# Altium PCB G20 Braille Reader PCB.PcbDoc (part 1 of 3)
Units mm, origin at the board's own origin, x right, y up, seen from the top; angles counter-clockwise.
Board outline 160.1 x 170.2 mm, 2 copper layers (Top Layer, Bottom Layer); 206 components, 272 nets, 975 pads, 345 vias.
Unrouted connection lines stored in the file: 1.
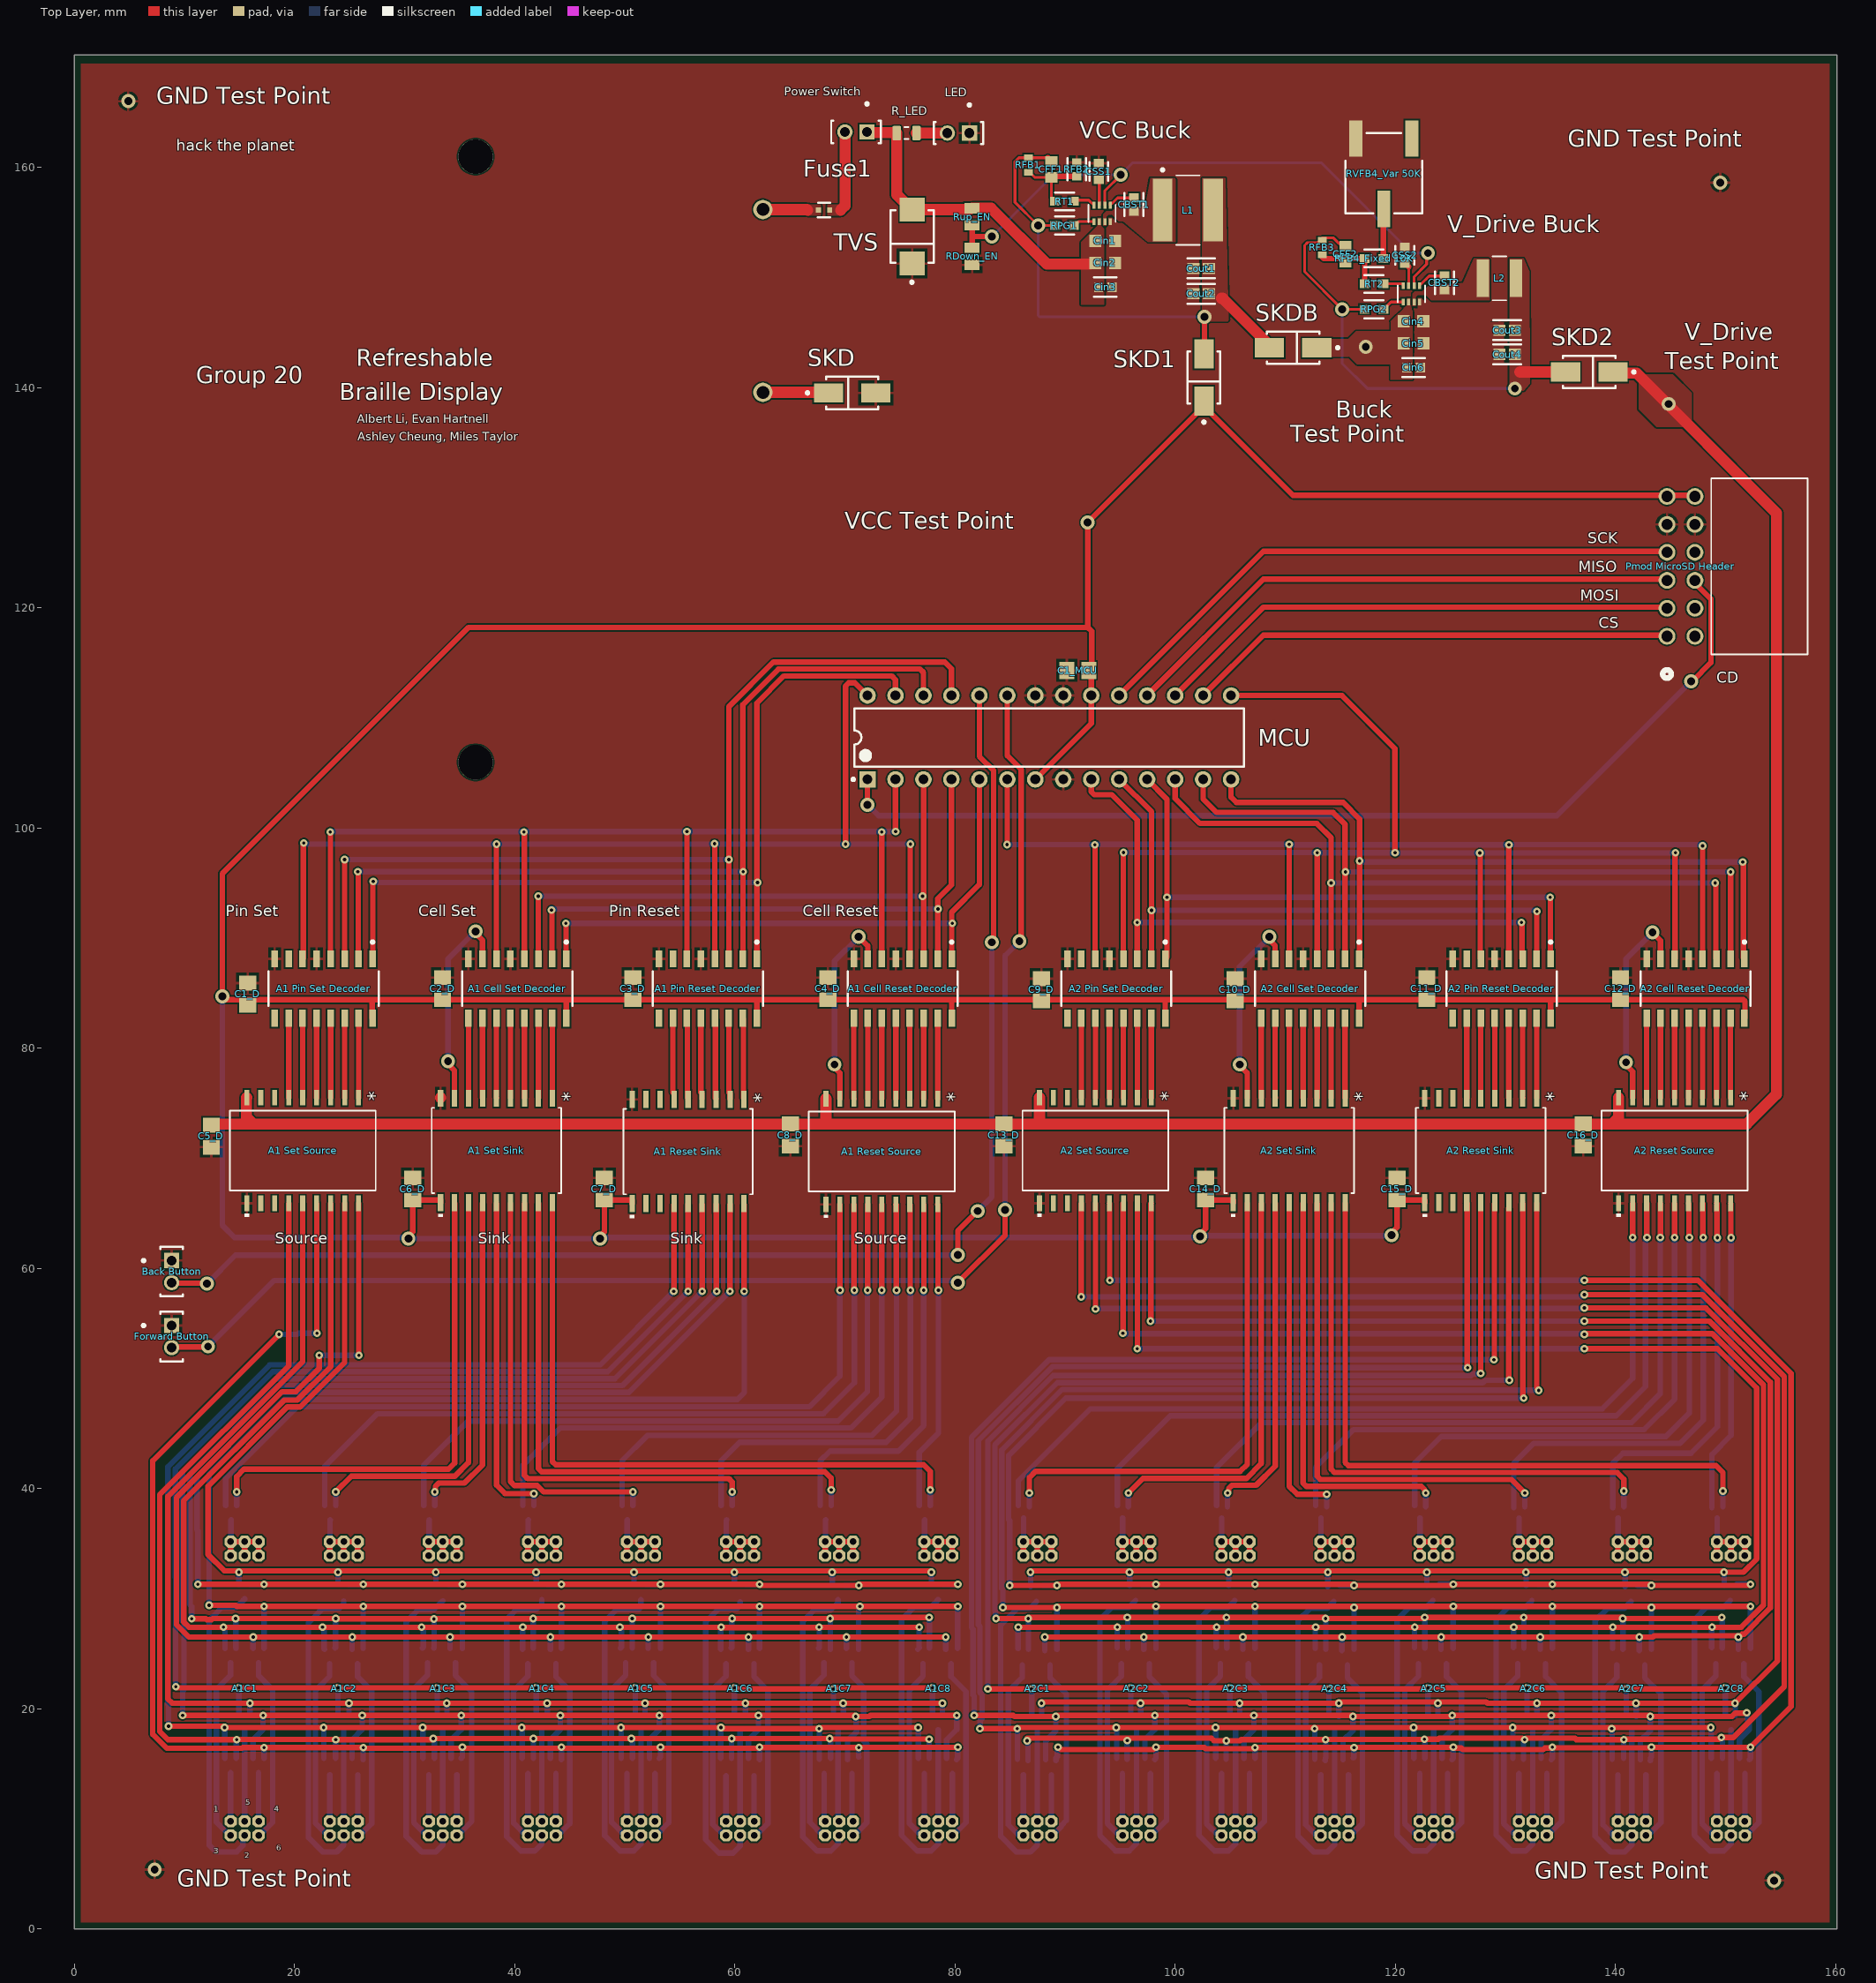
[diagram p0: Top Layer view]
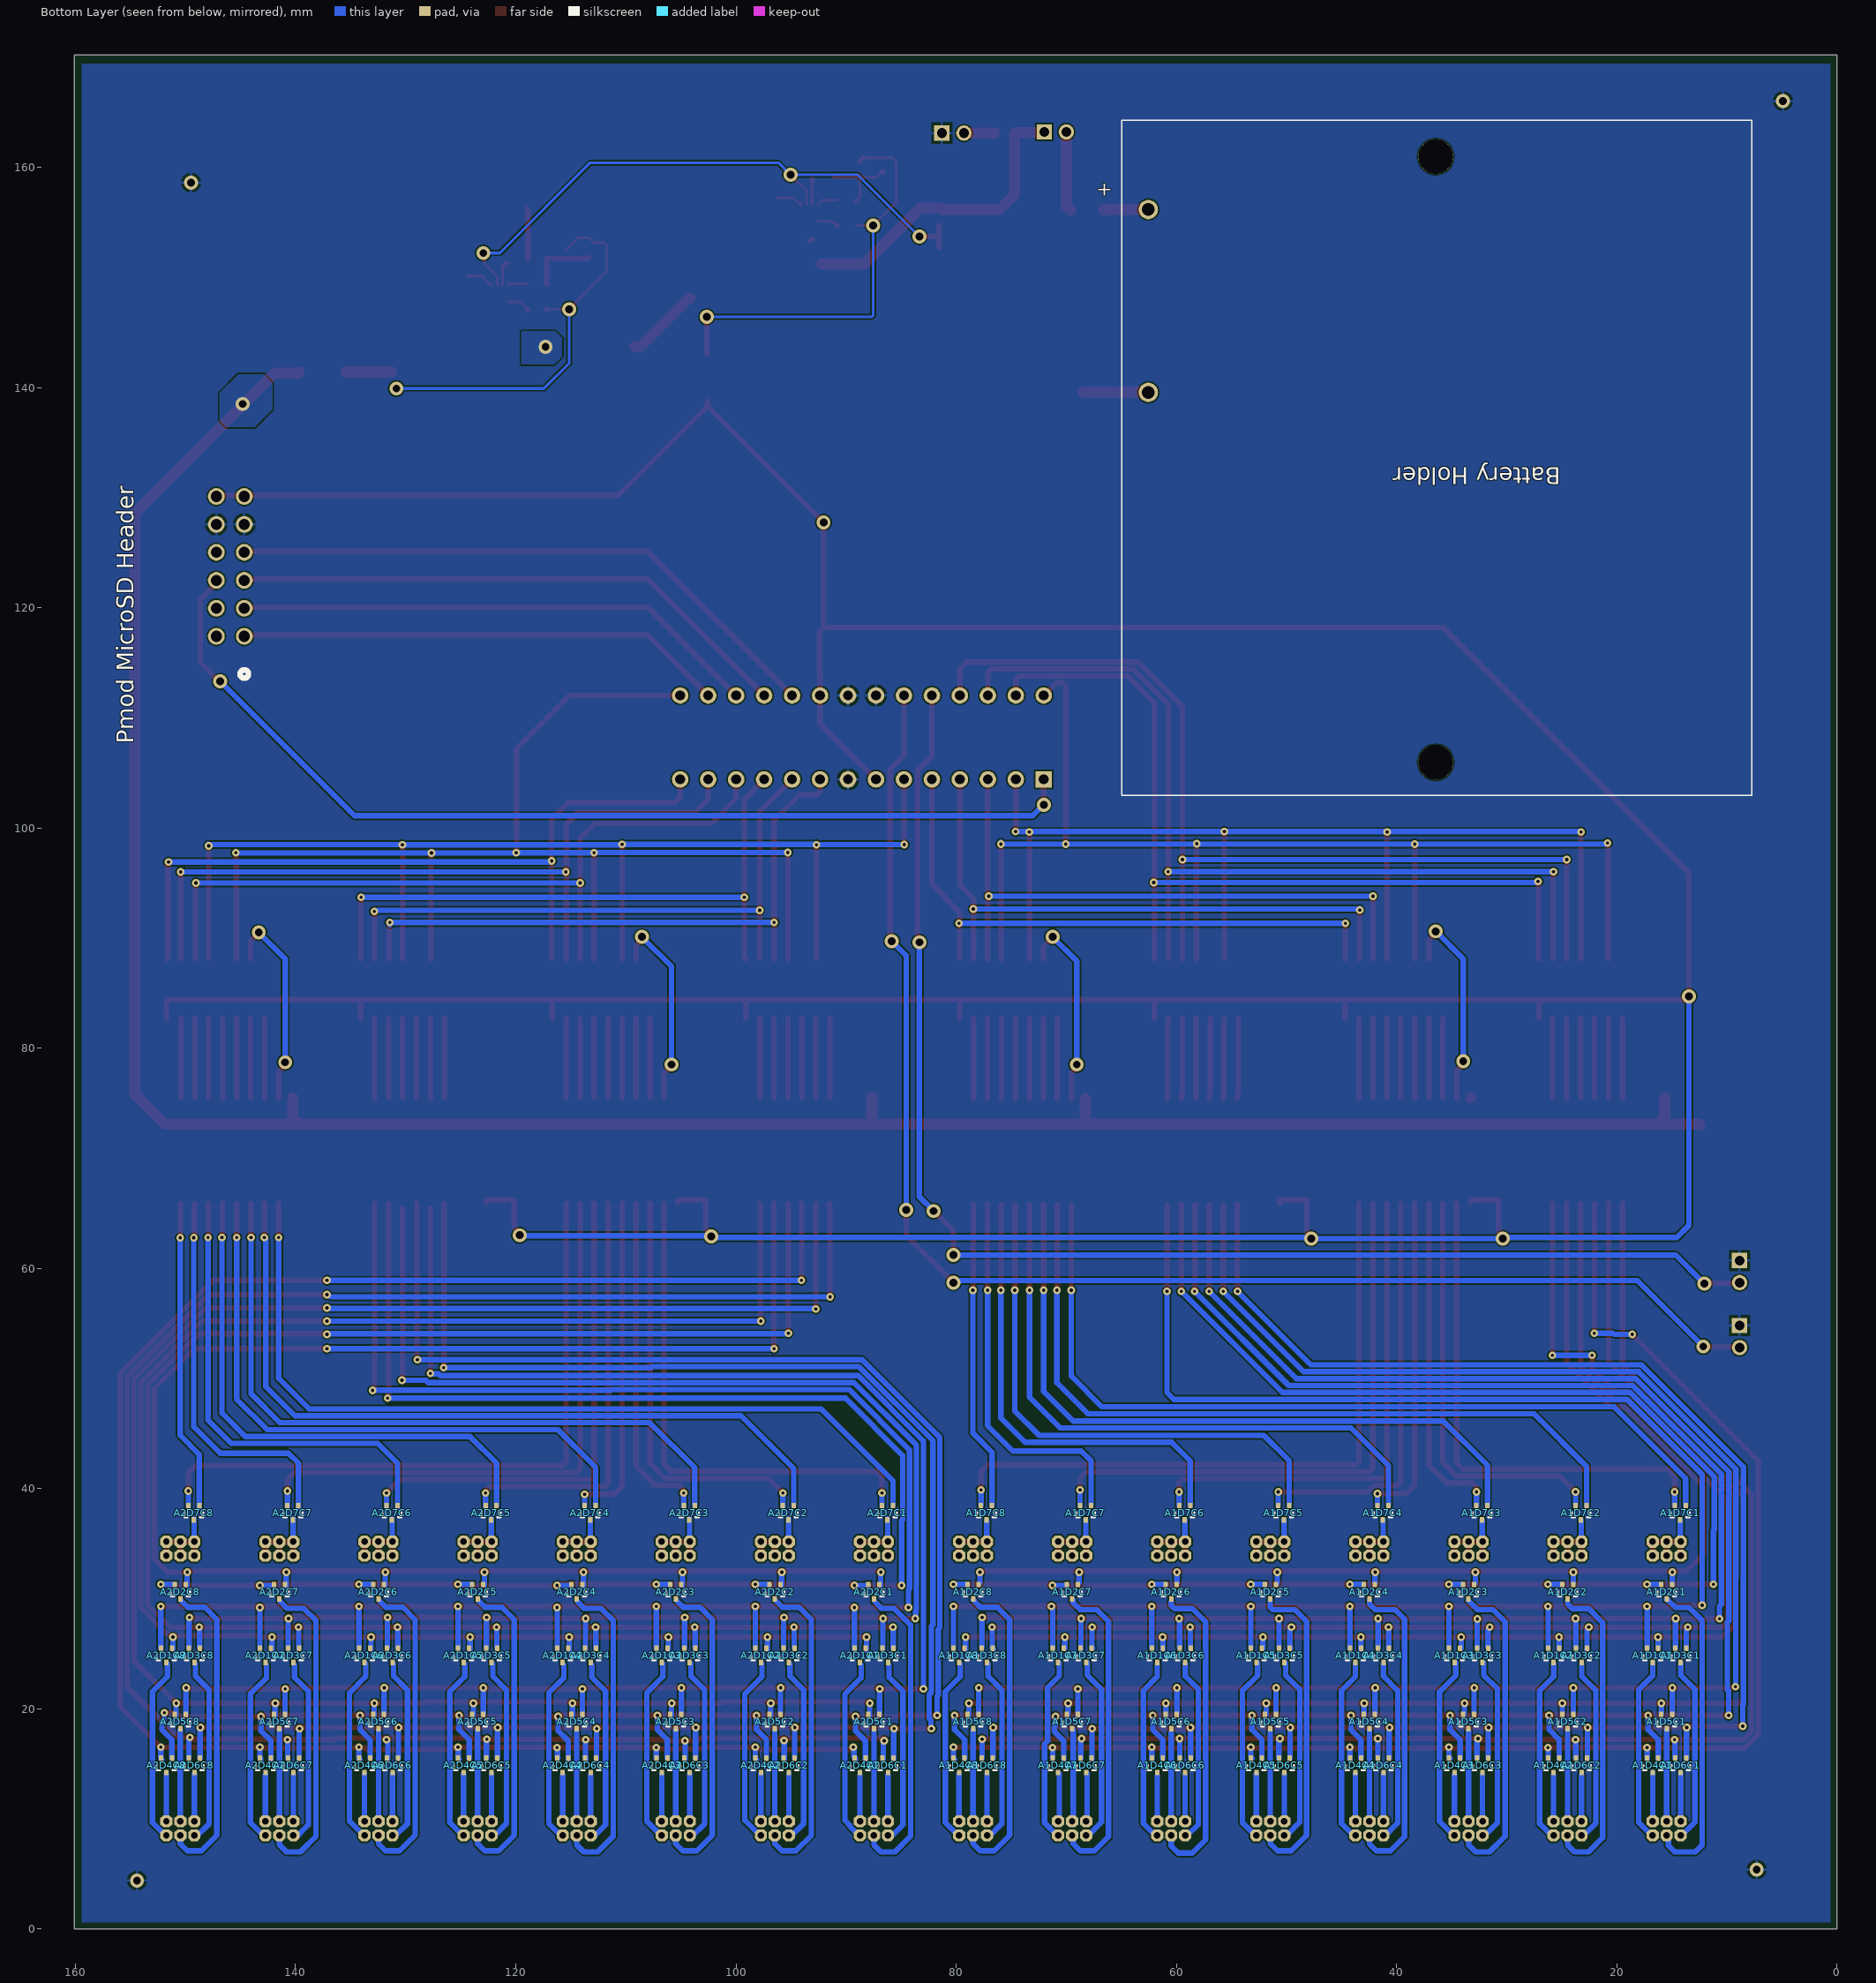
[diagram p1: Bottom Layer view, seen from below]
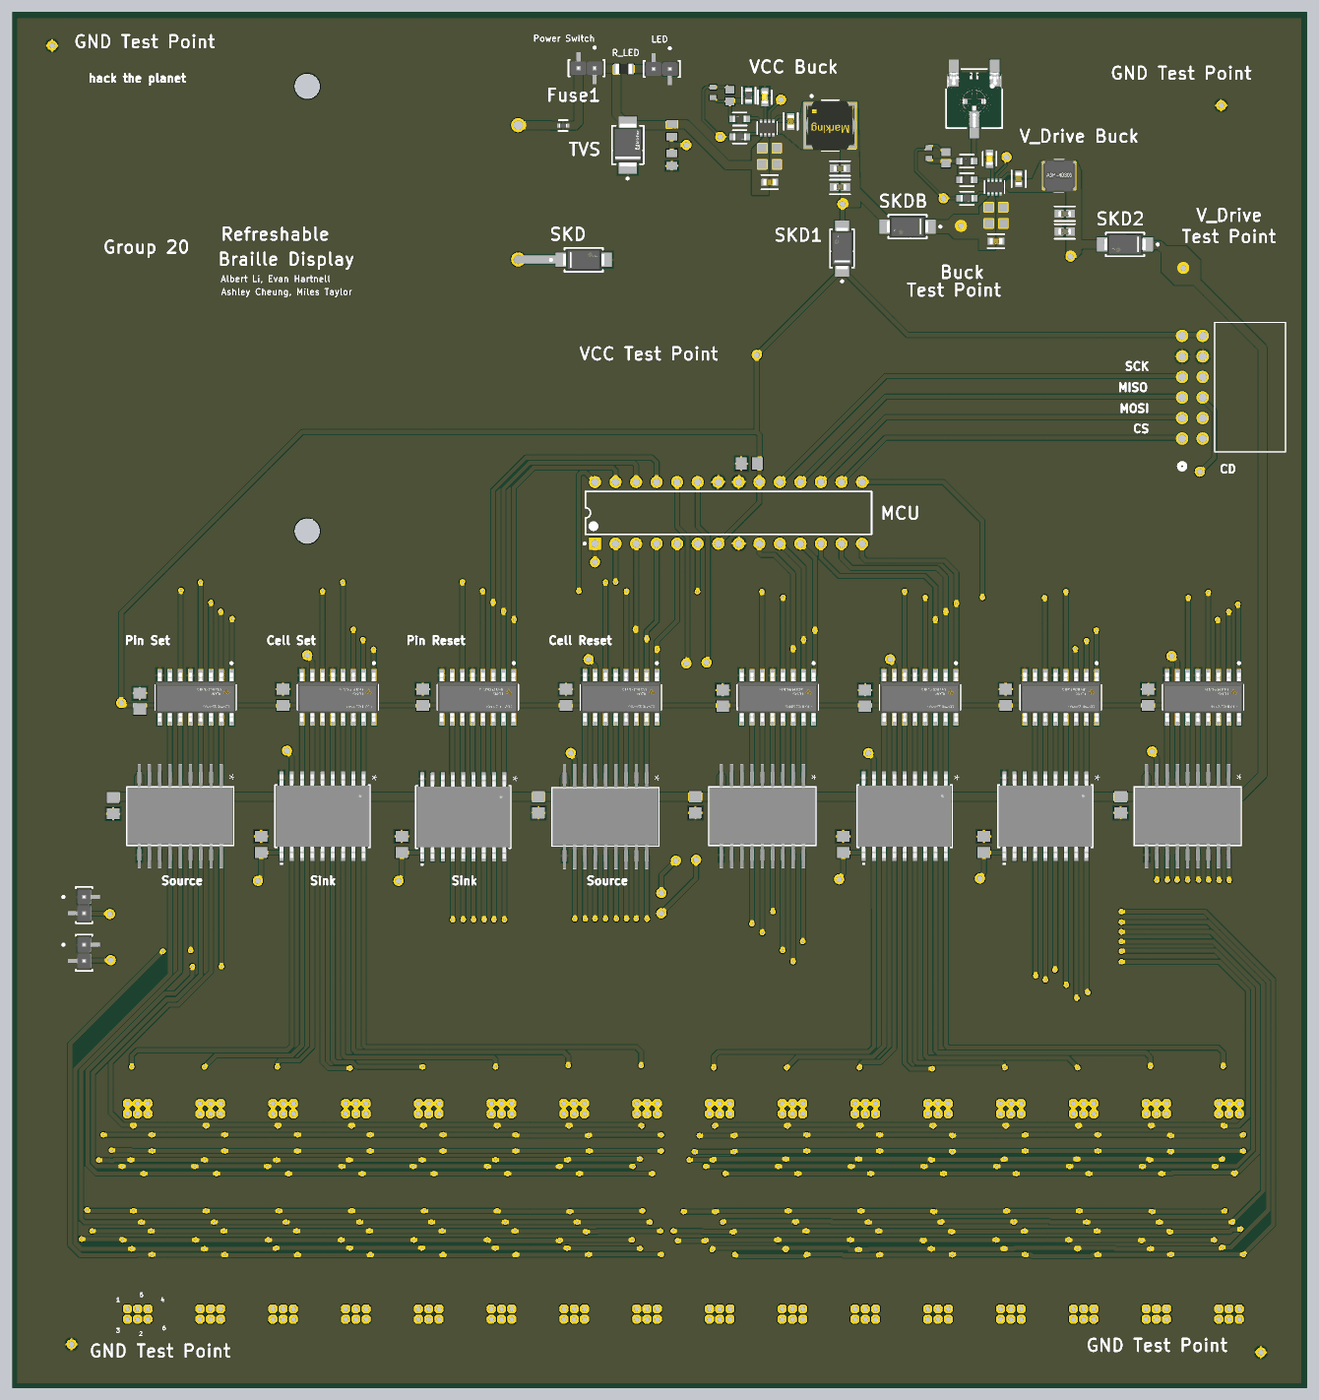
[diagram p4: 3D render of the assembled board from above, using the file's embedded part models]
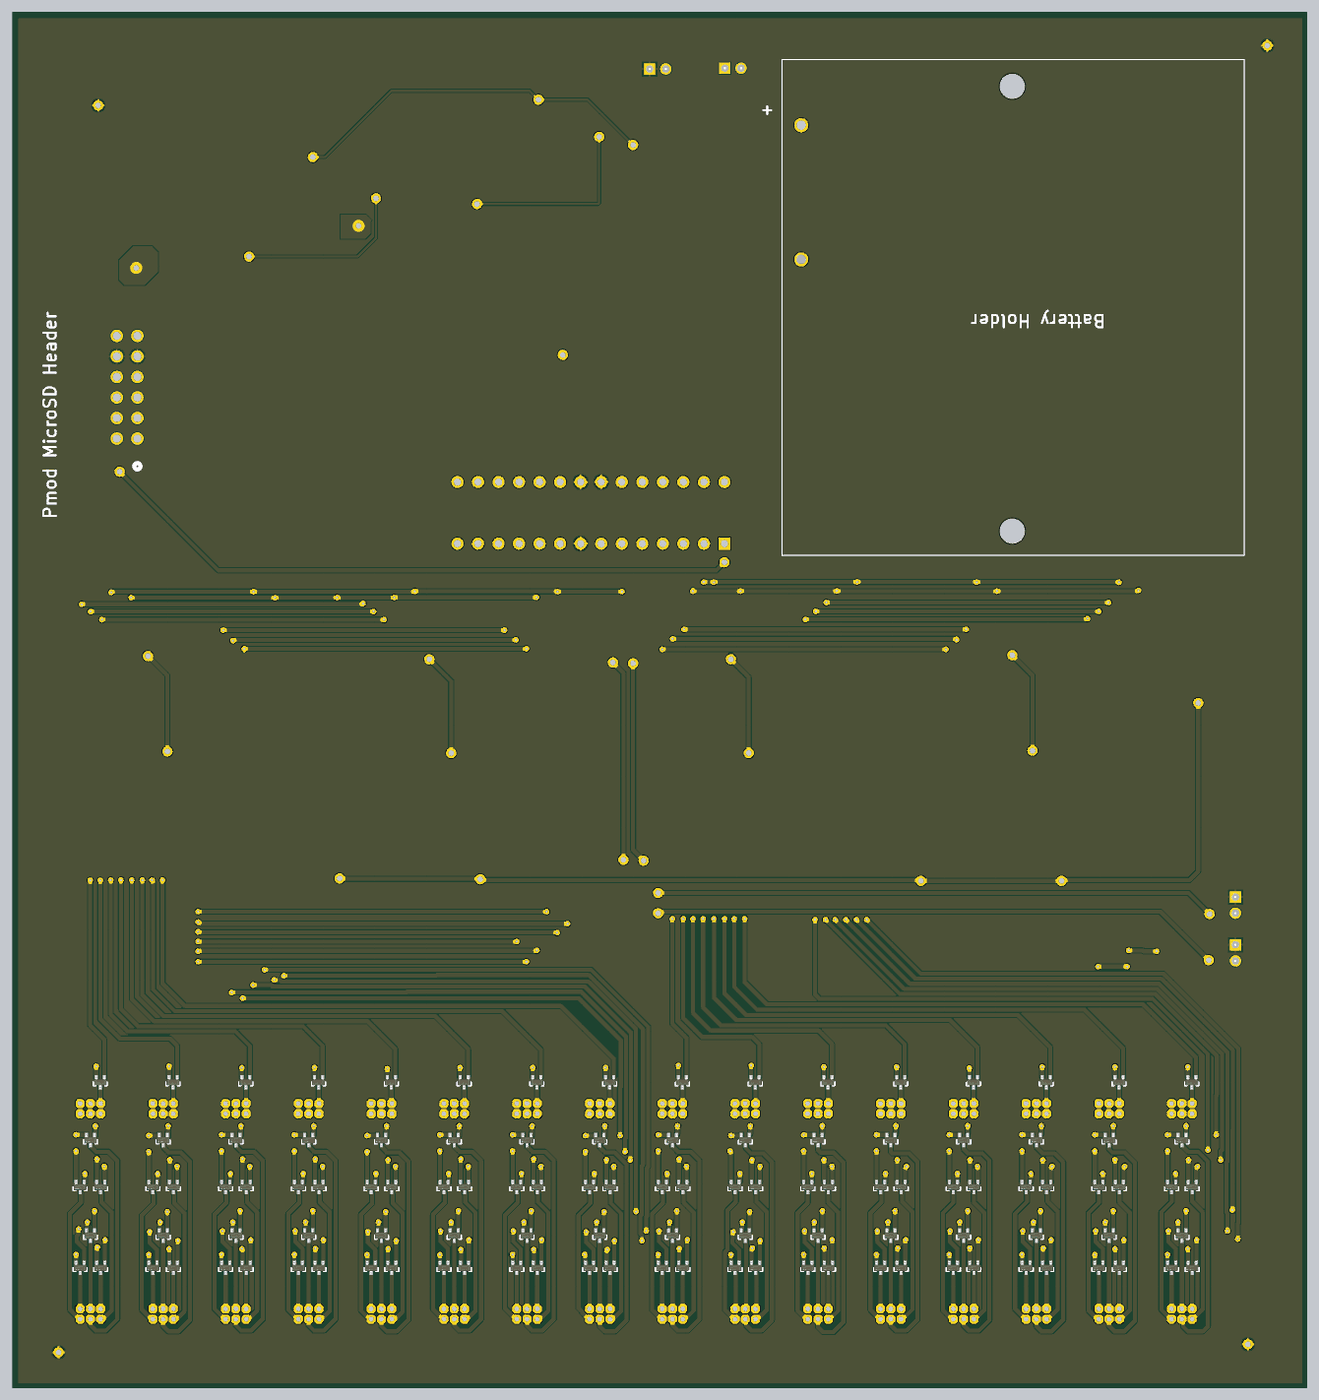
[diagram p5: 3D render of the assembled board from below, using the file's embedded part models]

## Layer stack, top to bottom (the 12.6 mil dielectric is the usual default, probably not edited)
Top Solder: solder mask 0.0102, Solder Resist, Dk 3.5
Top Layer: signal copper 0.0356
Dielectric 1: dielectric 0.32, FR-4, Dk 4.8
Bottom Layer: signal copper 0.0356
Bottom Solder: solder mask 0.0102, Solder Resist, Dk 3.5

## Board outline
0,0 0,170.2 160.1,170.2 160.1,0

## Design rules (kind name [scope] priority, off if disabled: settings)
BoardOutlineClearance [All] p1: gap=0.5 ignorepadtopadclearanceinfootprint=FALSE
Clearance [All] p1: gap=0.127 ignorepadtopadclearanceinfootprint=TRUE
HoleSize [All] p1: absolutevalues=TRUE maxlimit=40 minlimit=0.3 maxpercent=80.000 minpercent=20.000
MinimumAnnularRing [All] p1: minimumring=0.18
MinimumSolderMaskSliver [All] p1: minsoldermaskwidth=0.2
PolygonConnect [All] p1: connectstyle=Relief reliefconductorwidth=0.254 reliefentries=4 polygonreliefangle="90 Angle" airgapwidth=0.254
RoutingVias [All] p1: holewidth=0.3 width=0.6 viastyle="Through Hole" minholewidth=0.18 minwidth=0.6 maxholewidth=0.711 maxwidth=1.27
SolderMaskExpansion [All] p1: expansion=0.102 istentingtop=FALSE
SupplyNets "Schematic Supply Nets_13" [InNet('VCC1')] p1: voltage=0.000
SupplyNets "Schematic Supply Nets_4" [InNet('V_Drive1')] p2: voltage=0.000
SupplyNets "Schematic Supply Nets_1" [InNet('VCC_Filtered')] p3: voltage=0.000
SupplyNets "Schematic Supply Nets_12" [InNet('VSW2')] p4: voltage=0.000
SupplyNets "Schematic Supply Nets_11" [InNet('VPG1')] p5: voltage=0.000
SupplyNets "Schematic Supply Nets_10" [InNet('Vin')] p6: voltage=0.000
SupplyNets "Schematic Supply Nets_9" [InNet('VSW1')] p7: voltage=0.000
SupplyNets "Schematic Supply Nets_8" [InNet('VFB1')] p8: voltage=0.000
SupplyNets "Schematic Supply Nets_7" [InNet('VEN_Buck')] p9: voltage=0.000
SupplyNets "Schematic Supply Nets_6" [InNet('VFB2')] p10: voltage=0.000
SupplyNets "Schematic Supply Nets_5" [InNet('VPG2')] p11: voltage=0.000
SupplyNets "Schematic Supply Nets_3" [InNet('VCC')] p12: voltage=0.000
SupplyNets "Schematic Supply Nets_2" [InNet('GND')] p13: voltage=0.000
SupplyNets "Schematic Supply Nets" [InNet('V_Drive')] p14: voltage=0.000
Width [All] p1: maxlimit=1.016 minlimit=0.127 preferedwidth=1.016 bottomlayer_prefwidth=0.254 minimp=50.000000 maximp=50.000000 favimp=50.000000
28 further rules are at their usual default settings.

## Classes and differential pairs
component class "Power and Voltage Regulation Schematic": "Battery Holder" CBST1 CBST2 CFF1 CFF2 Cin1 Cin2 Cin3 Cin4 Cin5 Cin6 Cout1 Cout2 Cout3 Cout4 CSS1 CSS2 Fuse1 L1 L2 LED "Power Switch" R_LED RDown_EN RFB1 RFB2 RFB3 "RFB4_Fixed 10K" RPG1 RPG2 RT1 RT2 Rup_EN "RVFB4_Var 50K" SKD SKD1 SKD2 SKDB TVS "V_Drive Buck" "VCC Buck"
component class "MCU Schematic": "Back Button" C1_MCU "Forward Button" MCU "Pmod MicroSD Header"
component class "Array 2 Cell Driving Schematic": "A2 Cell Reset Decoder" "A2 Cell Set Decoder" "A2 Pin Reset Decoder" "A2 Pin Set Decoder" "A2 Reset Sink" "A2 Reset Source" "A2 Set Sink" "A2 Set Source" C9_D C10_D C11_D C12_D C13_D C14_D C15_D C16_D
component class "Array 2 Braille Cell Schematic": "119.724 mm" A2C1 A2C2 A2C3 A2C4 A2C5 A2C6 A2C7 A2C8 A2D1C1 A2D1C2 A2D1C3 A2D1C4 A2D1C5 A2D1C6 A2D1C7 A2D1C8 A2D2C1 A2D2C2 A2D2C3 A2D2C4 A2D2C5 A2D2C6 A2D2C7 A2D2C8 A2D3C1 A2D3C2 A2D3C3 A2D3C4 A2D3C5 A2D3C6 A2D3C7 A2D3C8 A2D4C1 A2D4C2 A2D4C3 A2D4C4 A2D4C5 A2D4C6 A2D4C7 A2D4C8 A2D5C1 A2D5C2 A2D5C3 A2D5C4 A2D5C5 A2D5C6 A2D5C7 A2D5C8 A2D6C1 A2D6C2 A2D6C3 A2D6C4 A2D6C5 A2D6C6 A2D6C7 A2D6C8 A2D7C1 A2D7C2 A2D7C3 A2D7C4 A2D7C5 A2D7C6 A2D7C7 A2D7C8
component class "Array 1 Cell Driving Schematic": "A1 Cell Reset Decoder" "A1 Cell Set Decoder" "A1 Pin Reset Decoder" "A1 Pin Set Decoder" "A1 Reset Sink" "A1 Reset Source" "A1 Set Sink" "A1 Set Source" C1_D C2_D C3_D C4_D C5_D C6_D C7_D C8_D
component class "Array 1 Braille Cell Schematic": A1C1 A1C2 A1C3 A1C4 A1C5 A1C6 A1C7 A1C8 A1D1C1 A1D1C2 A1D1C3 A1D1C4 A1D1C5 A1D1C6 A1D1C7 A1D1C8 A1D2C1 A1D2C2 A1D2C3 A1D2C4 A1D2C5 A1D2C6 A1D2C7 A1D2C8 A1D3C1 A1D3C2 A1D3C3 A1D3C4 A1D3C5 A1D3C6 A1D3C7 A1D3C8 A1D4C1 A1D4C2 A1D4C3 A1D4C4 A1D4C5 A1D4C6 A1D4C7 A1D4C8 A1D5C1 A1D5C2 A1D5C3 A1D5C4 A1D5C5 A1D5C6 A1D5C7 A1D5C8 A1D6C1 A1D6C2 A1D6C3 A1D6C4 A1D6C5 A1D6C6 A1D6C7 A1D6C8 A1D7C1 A1D7C2 A1D7C3 A1D7C4 A1D7C5 A1D7C6 A1D7C7 A1D7C8

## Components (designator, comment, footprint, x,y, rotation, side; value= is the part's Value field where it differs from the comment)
"A1 Cell Reset Decoder" "CD74HC238M96" FP-D0016A-MFG 75.246,85.405 r270 top
"A1 Cell Set Decoder" "CD74HC238M96" FP-D0016A-MFG 40.246,85.405 r270 top
"A1 Pin Reset Decoder" "CD74HC238M96" FP-D0016A-MFG 57.546,85.405 r270 top
"A1 Pin Set Decoder" "CD74HC238M96" FP-D0016A-MFG 22.646,85.405 r270 top
"A1 Reset Sink" "TBD62083AFWG,EL" P-SOP18-0812-1p27-001_TOS 55.746,70.605 r270 top
"A1 Reset Source" "TBD62783AFG,EL" SOP18-P-375-1p27_TOS 73.346,70.605 r270 top
"A1 Set Sink" "TBD62083AFWG,EL" P-SOP18-0812-1p27-001_TOS 38.346,70.705 r270 top
"A1 Set Source" "TBD62783AFG,EL" SOP18-P-375-1p27_TOS 20.746,70.705 r270 top
A1C1 "Braille Cell" BRAILLE-6 15.47,21.842 r180 top
A1C2 "Braille Cell" BRAILLE-6 24.47,21.842 r180 top
A1C3 "Braille Cell" BRAILLE-6 33.47,21.842 r180 top
A1C4 "Braille Cell" BRAILLE-6 42.47,21.842 r180 top
A1C5 "Braille Cell" BRAILLE-6 51.47,21.842 r180 top
A1C6 "Braille Cell" BRAILLE-6 60.47,21.842 r180 top
A1C7 "Braille Cell" BRAILLE-6 69.47,21.842 r180 top
A1C8 "Braille Cell" BRAILLE-6 78.47,21.842 r180 top
A1D1C1 "BAV99T-7-F" FP-SOT523-MFG 16.735,24.842 r270 bottom value=1.5pF
A1D1C2 "BAV99T-7-F" FP-SOT523-MFG 25.735,24.842 r270 bottom value=1.5pF
A1D1C3 "BAV99T-7-F" FP-SOT523-MFG 34.735,24.842 r270 bottom value=1.5pF
A1D1C4 "BAV99T-7-F" FP-SOT523-MFG 43.735,24.842 r270 bottom value=1.5pF
A1D1C5 "BAV99T-7-F" FP-SOT523-MFG 52.735,24.842 r270 bottom value=1.5pF
A1D1C6 "BAV99T-7-F" FP-SOT523-MFG 61.735,24.842 r270 bottom value=1.5pF
A1D1C7 "BAV99T-7-F" FP-SOT523-MFG 70.735,24.842 r270 bottom value=1.5pF
A1D1C8 "BAV99T-7-F" FP-SOT523-MFG 79.735,24.842 r270 bottom value=1.5pF
A1D2C1 "BAV99T-7-F" FP-SOT523-MFG 15.465,30.639 r270 bottom value=1.5pF
A1D2C2 "BAV99T-7-F" FP-SOT523-MFG 24.465,30.639 r270 bottom value=1.5pF
A1D2C3 "BAV99T-7-F" FP-SOT523-MFG 33.465,30.639 r270 bottom value=1.5pF
A1D2C4 "BAV99T-7-F" FP-SOT523-MFG 42.465,30.639 r270 bottom value=1.5pF
A1D2C5 "BAV99T-7-F" FP-SOT523-MFG 51.465,30.639 r270 bottom value=1.5pF
A1D2C6 "BAV99T-7-F" FP-SOT523-MFG 60.465,30.639 r270 bottom value=1.5pF
A1D2C7 "BAV99T-7-F" FP-SOT523-MFG 69.465,30.639 r270 bottom value=1.5pF
A1D2C8 "BAV99T-7-F" FP-SOT523-MFG 78.465,30.639 r270 bottom value=1.5pF
A1D3C1 "BAV99T-7-F" FP-SOT523-MFG 14.195,24.842 r270 bottom value=1.5pF
A1D3C2 "BAV99T-7-F" FP-SOT523-MFG 23.195,24.842 r270 bottom value=1.5pF
A1D3C3 "BAV99T-7-F" FP-SOT523-MFG 32.195,24.842 r270 bottom value=1.5pF
A1D3C4 "BAV99T-7-F" FP-SOT523-MFG 41.195,24.842 r270 bottom value=1.5pF
A1D3C5 "BAV99T-7-F" FP-SOT523-MFG 50.195,24.842 r270 bottom value=1.5pF
A1D3C6 "BAV99T-7-F" FP-SOT523-MFG 59.195,24.842 r270 bottom value=1.5pF
A1D3C7 "BAV99T-7-F" FP-SOT523-MFG 68.195,24.842 r270 bottom value=1.5pF
A1D3C8 "BAV99T-7-F" FP-SOT523-MFG 77.195,24.842 r270 bottom value=1.5pF
A1D4C1 "BAV99T-7-F" FP-SOT523-MFG 16.735,14.86 r270 bottom value=1.5pF
A1D4C2 "BAV99T-7-F" FP-SOT523-MFG 25.735,14.86 r270 bottom value=1.5pF
A1D4C3 "BAV99T-7-F" FP-SOT523-MFG 34.735,14.86 r270 bottom value=1.5pF
A1D4C4 "BAV99T-7-F" FP-SOT523-MFG 43.735,14.86 r270 bottom value=1.5pF
A1D4C5 "BAV99T-7-F" FP-SOT523-MFG 52.735,14.86 r270 bottom value=1.5pF
A1D4C6 "BAV99T-7-F" FP-SOT523-MFG 61.735,14.86 r270 bottom value=1.5pF
A1D4C7 "BAV99T-7-F" FP-SOT523-MFG 70.735,14.86 r270 bottom value=1.5pF
A1D4C8 "BAV99T-7-F" FP-SOT523-MFG 79.735,14.86 r270 bottom value=1.5pF
A1D5C1 "BAV99T-7-F" FP-SOT523-MFG 15.465,18.842 r270 bottom value=1.5pF
A1D5C2 "BAV99T-7-F" FP-SOT523-MFG 24.465,18.842 r270 bottom value=1.5pF
A1D5C3 "BAV99T-7-F" FP-SOT523-MFG 33.465,18.842 r270 bottom value=1.5pF
A1D5C4 "BAV99T-7-F" FP-SOT523-MFG 42.465,18.842 r270 bottom value=1.5pF
A1D5C5 "BAV99T-7-F" FP-SOT523-MFG 51.465,18.842 r270 bottom value=1.5pF
A1D5C6 "BAV99T-7-F" FP-SOT523-MFG 60.465,18.842 r270 bottom value=1.5pF
A1D5C7 "BAV99T-7-F" FP-SOT523-MFG 69.465,18.842 r270 bottom value=1.5pF
A1D5C8 "BAV99T-7-F" FP-SOT523-MFG 78.465,18.842 r270 bottom value=1.5pF
A1D6C1 "BAV99T-7-F" FP-SOT523-MFG 14.195,14.86 r270 bottom value=1.5pF
A1D6C2 "BAV99T-7-F" FP-SOT523-MFG 23.195,14.86 r270 bottom value=1.5pF
A1D6C3 "BAV99T-7-F" FP-SOT523-MFG 32.195,14.86 r270 bottom value=1.5pF
A1D6C4 "BAV99T-7-F" FP-SOT523-MFG 41.195,14.86 r270 bottom value=1.5pF
A1D6C5 "BAV99T-7-F" FP-SOT523-MFG 50.195,14.86 r270 bottom value=1.5pF
A1D6C6 "BAV99T-7-F" FP-SOT523-MFG 59.195,14.86 r270 bottom value=1.5pF
A1D6C7 "BAV99T-7-F" FP-SOT523-MFG 68.195,14.86 r270 bottom value=1.5pF
A1D6C8 "BAV99T-7-F" FP-SOT523-MFG 77.195,14.86 r270 bottom value=1.5pF
A1D7C1 "BAV99T-7-F" FP-SOT523-MFG 14.246,37.805 r270 bottom value=1.5pF
A1D7C2 "BAV99T-7-F" FP-SOT523-MFG 23.246,37.805 r270 bottom value=1.5pF
A1D7C3 "BAV99T-7-F" FP-SOT523-MFG 32.246,37.805 r270 bottom value=1.5pF
A1D7C4 "BAV99T-7-F" FP-SOT523-MFG 41.246,37.805 r270 bottom value=1.5pF
A1D7C5 "BAV99T-7-F" FP-SOT523-MFG 50.246,37.805 r270 bottom value=1.5pF
A1D7C6 "BAV99T-7-F" FP-SOT523-MFG 59.246,37.805 r270 bottom value=1.5pF
A1D7C7 "BAV99T-7-F" FP-SOT523-MFG 68.246,37.805 r270 bottom value=1.5pF
A1D7C8 "BAV99T-7-F" FP-SOT523-MFG 77.246,37.805 r270 bottom value=1.5pF
"A2 Cell Reset Decoder" "CD74HC238M96" FP-D0016A-MFG 147.251,85.405 r270 top
"A2 Cell Set Decoder" "CD74HC238M96" FP-D0016A-MFG 112.246,85.405 r270 top
"A2 Pin Reset Decoder" "CD74HC238M96" FP-D0016A-MFG 129.646,85.405 r270 top
"A2 Pin Set Decoder" "CD74HC238M96" FP-D0016A-MFG 94.646,85.405 r270 top
"A2 Reset Sink" "TBD62083AFWG,EL" P-SOP18-0812-1p27-001_TOS 127.746,70.705 r270 top
"A2 Reset Source" "TBD62783AFG,EL" SOP18-P-375-1p27_TOS 145.346,70.705 r270 top
"A2 Set Sink" "TBD62083AFWG,EL" P-SOP18-0812-1p27-001_TOS 110.346,70.705 r270 top
"A2 Set Source" "TBD62783AFG,EL" SOP18-P-375-1p27_TOS 92.746,70.705 r270 top
A2C1 "Braille Cell" BRAILLE-6 87.47,21.842 r180 top
A2C2 "Braille Cell" BRAILLE-6 96.47,21.842 r180 top
A2C3 "Braille Cell" BRAILLE-6 105.47,21.842 r180 top
A2C4 "Braille Cell" BRAILLE-6 114.47,21.842 r180 top
A2C5 "Braille Cell" BRAILLE-6 123.47,21.842 r180 top
A2C6 "Braille Cell" BRAILLE-6 132.47,21.842 r180 top
A2C7 "Braille Cell" BRAILLE-6 141.47,21.842 r180 top
A2C8 "Braille Cell" BRAILLE-6 150.47,21.842 r180 top
A2D1C1 "BAV99T-7-F" FP-SOT523-MFG 88.735,24.842 r270 bottom value=1.5pF
A2D1C2 "BAV99T-7-F" FP-SOT523-MFG 97.735,24.842 r270 bottom value=1.5pF
A2D1C3 "BAV99T-7-F" FP-SOT523-MFG 106.735,24.842 r270 bottom value=1.5pF
A2D1C4 "BAV99T-7-F" FP-SOT523-MFG 115.735,24.842 r270 bottom value=1.5pF
A2D1C5 "BAV99T-7-F" FP-SOT523-MFG 124.735,24.842 r270 bottom value=1.5pF
A2D1C6 "BAV99T-7-F" FP-SOT523-MFG 133.735,24.842 r270 bottom value=1.5pF
A2D1C7 "BAV99T-7-F" FP-SOT523-MFG 142.735,24.842 r270 bottom value=1.5pF
A2D1C8 "BAV99T-7-F" FP-SOT523-MFG 151.735,24.842 r270 bottom value=1.5pF
A2D2C1 "BAV99T-7-F" FP-SOT523-MFG 87.465,30.639 r270 bottom value=1.5pF
A2D2C2 "BAV99T-7-F" FP-SOT523-MFG 96.465,30.639 r270 bottom value=1.5pF
A2D2C3 "BAV99T-7-F" FP-SOT523-MFG 105.465,30.639 r270 bottom value=1.5pF
A2D2C4 "BAV99T-7-F" FP-SOT523-MFG 114.465,30.639 r270 bottom value=1.5pF
A2D2C5 "BAV99T-7-F" FP-SOT523-MFG 123.465,30.639 r270 bottom value=1.5pF
A2D2C6 "BAV99T-7-F" FP-SOT523-MFG 132.465,30.639 r270 bottom value=1.5pF
A2D2C7 "BAV99T-7-F" FP-SOT523-MFG 141.465,30.639 r270 bottom value=1.5pF
A2D2C8 "BAV99T-7-F" FP-SOT523-MFG 150.465,30.639 r270 bottom value=1.5pF
A2D3C1 "BAV99T-7-F" FP-SOT523-MFG 86.195,24.842 r270 bottom value=1.5pF
A2D3C2 "BAV99T-7-F" FP-SOT523-MFG 95.195,24.842 r270 bottom value=1.5pF
A2D3C3 "BAV99T-7-F" FP-SOT523-MFG 104.195,24.842 r270 bottom value=1.5pF
A2D3C4 "BAV99T-7-F" FP-SOT523-MFG 113.195,24.842 r270 bottom value=1.5pF
A2D3C5 "BAV99T-7-F" FP-SOT523-MFG 122.195,24.842 r270 bottom value=1.5pF
A2D3C6 "BAV99T-7-F" FP-SOT523-MFG 131.195,24.842 r270 bottom value=1.5pF
A2D3C7 "BAV99T-7-F" FP-SOT523-MFG 140.195,24.842 r270 bottom value=1.5pF
A2D3C8 "BAV99T-7-F" FP-SOT523-MFG 149.195,24.842 r270 bottom value=1.5pF
A2D4C1 "BAV99T-7-F" FP-SOT523-MFG 88.735,14.86 r270 bottom value=1.5pF
A2D4C2 "BAV99T-7-F" FP-SOT523-MFG 97.735,14.86 r270 bottom value=1.5pF
A2D4C3 "BAV99T-7-F" FP-SOT523-MFG 106.735,14.86 r270 bottom value=1.5pF
A2D4C4 "BAV99T-7-F" FP-SOT523-MFG 115.735,14.86 r270 bottom value=1.5pF
A2D4C5 "BAV99T-7-F" FP-SOT523-MFG 124.735,14.86 r270 bottom value=1.5pF
A2D4C6 "BAV99T-7-F" FP-SOT523-MFG 133.735,14.86 r270 bottom value=1.5pF
A2D4C7 "BAV99T-7-F" FP-SOT523-MFG 142.735,14.86 r270 bottom value=1.5pF
A2D4C8 "BAV99T-7-F" FP-SOT523-MFG 151.735,14.86 r270 bottom value=1.5pF
A2D5C1 "BAV99T-7-F" FP-SOT523-MFG 87.465,18.842 r270 bottom value=1.5pF
A2D5C2 "BAV99T-7-F" FP-SOT523-MFG 96.465,18.842 r270 bottom value=1.5pF
A2D5C3 "BAV99T-7-F" FP-SOT523-MFG 105.465,18.842 r270 bottom value=1.5pF
A2D5C4 "BAV99T-7-F" FP-SOT523-MFG 114.465,18.842 r270 bottom value=1.5pF
A2D5C5 "BAV99T-7-F" FP-SOT523-MFG 123.465,18.842 r270 bottom value=1.5pF
A2D5C6 "BAV99T-7-F" FP-SOT523-MFG 132.465,18.842 r270 bottom value=1.5pF
A2D5C7 "BAV99T-7-F" FP-SOT523-MFG 141.465,18.842 r270 bottom value=1.5pF
A2D5C8 "BAV99T-7-F" FP-SOT523-MFG 150.465,18.842 r270 bottom value=1.5pF
A2D6C1 "BAV99T-7-F" FP-SOT523-MFG 86.195,14.86 r270 bottom value=1.5pF
A2D6C2 "BAV99T-7-F" FP-SOT523-MFG 95.195,14.86 r270 bottom value=1.5pF
A2D6C3 "BAV99T-7-F" FP-SOT523-MFG 104.195,14.86 r270 bottom value=1.5pF
A2D6C4 "BAV99T-7-F" FP-SOT523-MFG 113.195,14.86 r270 bottom value=1.5pF
A2D6C5 "BAV99T-7-F" FP-SOT523-MFG 122.195,14.86 r270 bottom value=1.5pF
A2D6C6 "BAV99T-7-F" FP-SOT523-MFG 131.195,14.86 r270 bottom value=1.5pF
A2D6C7 "BAV99T-7-F" FP-SOT523-MFG 140.195,14.86 r270 bottom value=1.5pF
A2D6C8 "BAV99T-7-F" FP-SOT523-MFG 149.195,14.86 r270 bottom value=1.5pF
A2D7C1 "BAV99T-7-F" FP-SOT523-MFG 86.246,37.805 r270 bottom value=1.5pF
A2D7C2 "BAV99T-7-F" FP-SOT523-MFG 95.246,37.805 r270 bottom value=1.5pF
A2D7C3 "BAV99T-7-F" FP-SOT523-MFG 104.246,37.805 r270 bottom value=1.5pF
A2D7C4 "BAV99T-7-F" FP-SOT523-MFG 113.246,37.805 r270 bottom value=1.5pF
A2D7C5 "BAV99T-7-F" FP-SOT523-MFG 122.246,37.805 r270 bottom value=1.5pF
A2D7C6 "BAV99T-7-F" FP-SOT523-MFG 131.246,37.805 r270 bottom value=1.5pF
A2D7C7 "BAV99T-7-F" FP-SOT523-MFG 140.246,37.805 r270 bottom value=1.5pF
A2D7C8 "BAV99T-7-F" FP-SOT523-MFG 149.246,37.805 r270 bottom value=1.5pF
"Back Button" "TMM-102-03-T-S" FP-TMM-102-03-T-S-MFG 8.846,59.705 r270 top
"Battery Holder" "BC4AAPC" BAT_BC4AAPC 36.346,133.605 r0 bottom (schematic designator BT)
C1_D "100nF" CAPC0805(2012)100_M 15.746,84.905 r90 top
C1_MCU "100nF" CAPC0805(2012)100_M 91.146,114.305 r0 top
C2_D "100nF" CAPC0805(2012)100_M 33.446,85.405 r90 top
C3_D "100nF" CAPC0805(2012)100_M 50.746,85.405 r90 top
C4_D "100nF" CAPC0805(2012)100_M 68.446,85.405 r90 top
C5_D "100nF" CAPC0805(2012)100_M 12.446,72.005 r90 top
C6_D "100nF" CAPC0805(2012)100_M 30.746,67.205 r270 top
C7_D "100nF" CAPC0805(2012)100_M 48.146,67.205 r270 top
C8_D "100nF" CAPC0805(2012)100_M 65.046,72.105 r90 top
C9_D "100nF" CAPC0805(2012)100_M 87.846,85.305 r90 top
C10_D "100nF" CAPC0805(2012)100_M 105.446,85.305 r90 top
C11_D "100nF" CAPC0805(2012)100_M 122.846,85.405 r90 top
C12_D "100nF" CAPC0805(2012)100_M 140.446,85.405 r90 top
C13_D "100nF" CAPC0805(2012)100_M 84.446,72.105 r90 top
C14_D "100nF" CAPC0805(2012)100_M 102.746,67.205 r270 top
C15_D "100nF" CAPC0805(2012)100_M 120.146,67.205 r270 top
C16_D "100nF" CAPC0805(2012)100_M 137.046,72.105 r90 top
CBST1 "0.1uF" FP-0603B104K500CT-IPC_C 96.246,156.605 r270 top
CBST2 "0.1uF" FP-0603B104K500CT-IPC_C 124.446,149.505 r270 top
CFF1 "470pF" CAPC1608X92X38ML15T08 88.746,159.805 r90 top
CFF2 "470pF" CAPC1608X92X38ML15T08 115.446,152.105 r90 top
Cin1 "10uF" CAPC0603(1608)100_M 93.635,153.305 r180 top
Cin2 "10uF" CAPC0603(1608)100_M 93.635,151.305 r180 top
Cin3 "0.1uF" FP-0603B104K500CT-IPC_C 93.646,149.105 r0 top
Cin4 "10uF" CAPC0603(1608)100_M 121.635,146.005 r180 top
Cin5 "10uF" CAPC0603(1608)100_M 121.646,144.005 r180 top
Cin6 "0.1uF" FP-0603B104K500CT-IPC_C 121.646,141.805 r0 top
Cout1 "22uF" FP-GRM188-0_2-IPC_B 102.346,150.805 r180 top
Cout2 "22uF" FP-GRM188-0_2-IPC_B 102.346,148.505 r180 top
Cout3 "22uF" FP-GRM188-0_2-IPC_B 130.146,145.205 r180 top
Cout4 "22uF" FP-GRM188-0_2-IPC_B 130.146,143.005 r180 top
CSS1 "22nF" FP-CC0603-DA-MFG 93.046,159.605 r90 top value="22 nF"
CSS2 "22nF" FP-CC0603-DA-MFG 120.846,152.005 r90 top value="22 nF"
"Forward Button" "TMM-102-03-T-S" FP-TMM-102-03-T-S-MFG 8.846,53.805 r270 top
Fuse1 "ERB-RD2R00X" FP-ERBRD-MFG 68.1,156.1 r0 top value=53mΩ
L1 "6.8uH" WE-LQS_6028 101.146,156.105 r180 top
L2 "4.7uH" IND_ASPI-4030S-4R7M-T 129.446,149.905 r0 top
LED "TMM-102-03-T-S" FP-TMM-102-03-T-S-MFG 80.3,163.1 r180 top
MCU "ATmega328P-PU" 28P3 88.556,108.215 r90 top
"Pmod MicroSD Header" "PPPC062LJBN-RC" CONN_PPPC062LJBN-RC_SUL 144.66,117.4 r90 top
"Power Switch" "TMM-102-03-T-S" FP-TMM-102-03-T-S-MFG 71,163.2 r180 top
R_LED "470R5J" RESC0805(2012)_L 75.6,163.1 r0 top value=470ohm
RDown_EN "33Kohm" RESC2013X70X40LL20T20 81.546,151.905 r90 top
RFB1 "51Kohm" RESC1608X55X25LL10T15 86.646,160.205 r90 top
RFB2 "9.09Kohm" FP-CR0603-IPC_C 91.046,159.805 r270 top
RFB3 "51Kohm" RESC1608X55X25LL10T15 113.346,152.705 r90 top
"RFB4_Fixed 10K" "10Kohm" FP-RT0603-MFG 118.046,151.705 r180 top value=10KΩ
RPG1 "100Kohm" FP-AC0603-MFG 89.946,154.705 r0 top
RPG2 "100Kohm" FP-AC0603-MFG 118.046,147.105 r0 top
RT1 "10Kohm" FP-RT0603-MFG 89.946,156.905 r180 top value=10KΩ
RT2 "10Kohm" FP-RT0603-MFG 118.046,149.405 r180 top value=10KΩ
Rup_EN "68Kohm" RESC2013X70X40LL20T20 81.546,155.505 r90 top
"RVFB4_Var 50K" "3361P-1-503GLF" FP-3361P-MFG 118.946,159.405 r180 top
SKD "SS14" FP-403AE-MFG 70.646,139.505 r180 top
SKD1 "SS14" FP-403AE-MFG 102.6,140.9 r270 top
SKD2 "SS14" FP-403AE-MFG 137.6,141.4 r0 top
SKDB "SS14" FP-403AE-MFG 110.7,143.6 r0 top
TVS "SMBJ12A" FP-SMBJ-MFG 76.1,153.7 r90 top
"V_Drive Buck" "MP2338GTL-Z" SOT583_MP2338_MNP 121.446,148.505 r90 top
"VCC Buck" "MP2338GTL-Z" SOT583_MP2338_MNP 93.346,155.805 r90 top

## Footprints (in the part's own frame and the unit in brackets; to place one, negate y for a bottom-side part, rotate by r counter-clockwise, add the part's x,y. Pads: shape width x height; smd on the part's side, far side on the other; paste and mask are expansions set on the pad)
28P3 [mm] "28-Pin Plastic Dual In-Line Package (PDIP)"
  rect 1.5x1.5 hole 0.9: 1(-3.81,16.51)
  round 1.5 hole 0.9: 2(-3.81,13.97) 3(-3.81,11.43) 4(-3.81,8.89) 5(-3.81,6.35) 6(-3.81,3.81) 7(-3.81,1.27) 8(-3.81,-1.27) 9(-3.81,-3.81) 10(-3.81,-6.35) 11(-3.81,-8.89) 12(-3.81,-11.43) 13(-3.81,-13.97) 14(-3.81,-16.51) 15(3.81,-16.51) 16(3.81,-13.97) 17(3.81,-11.43) 18(3.81,-8.89) 19(3.81,-6.35) 20(3.81,-3.81) 21(3.81,-1.27) 22(3.81,1.27) 23(3.81,3.81) 24(3.81,6.35) 25(3.81,8.89) 26(3.81,11.43) 27(3.81,13.97) 28(3.81,16.51)
  silkscreen extent -3.93,-17.7 2.65,17.93, body extent -3.6,-17.65 3.6,17.65, height 4.58
BAT_BC4AAPC [mm]
  round 1.755 hole 1.17: NEG(26.2,-5.95) POS(26.2,-22.55)
  round 3.15 hole 3.15 unplated: ""(0.1,-27.35) ""(0.1,27.65)
  silkscreen extent -28.6,-30.65 28.6,30.65
BRAILLE-6 [mm]
  oct 1.108x1.108 / inner round 1.024 / far side oct 1.108x1.108 hole 0.6: P$1(-1.27,13.335) P$2(1.27,-13.335) P$3(0,13.335) P$4(0,-13.335) P$5(1.27,13.335) P$6(-1.27,-13.335) P$7(-1.27,12.065) P$8(1.27,-12.065) P$9(0,12.065) P$10(0,-12.065) P$11(1.27,12.065) P$12(-1.27,-12.065)
CAPC0603(1608)100_M [mm] "Chip Capacitor, Body 1.6x0.8mm, Height 1.0mm, IPC Low Density"
  rect 1.1x1.1 smd: 1(-0.9,0) 2(0.9,0)
  body extent -0.87,-0.47 0.88,0.48, height 1
CAPC0805(2012)100_M [mm] "Chip Capacitor, Body 2.0x1.2mm, Height 1.0mm, IPC Low Density"
  rect 1.35x1.55 smd: 1(-1,0) 2(1,0)
  body extent -1.1,-0.72 1.1,0.72, height 1
CAPC1608X92X38ML15T08 [mm] "Chip Capacitor, 2-Leads, Body 1.60x0.80mm, IPC Low Density"
  rect 0.95x1.1 smd: 1(-0.725,0) 2(0.725,0)
  body extent -0.87,-0.48 0.87,0.47, height 0.92
CONN_PPPC062LJBN-RC_SUL [mil]
  round 60 hole 40 paste-99999 mask+0: 1(0,0) 2(100,0) 3(200,0) 4(300,0) 5(400,0) 6(500,0) 7(0,-100) 8(100,-100) 9(200,-100) 10(300,-100) 11(400,-100) 12(500,-100)
  silkscreen extent -150,-503 565,15
FP-403AE-MFG [mm]
  rect 2.65x1.75 smd paste+0 mask+0: 1(-2.15,0) 2(2.15,0)
  silkscreen extent -2.37,-1.48 4.17,1.48, body extent -3.57,-1.58 3.57,1.58, height 0.25
FP-0603B104K500CT-IPC_C [mm]
  rect 0.832x0.86 smd paste+0 mask+0: 1(-0.614,0) 2(0.614,0)
  silkscreen extent -1.03,-0.87 1.03,0.87, body extent -1.13,-0.58 1.13,0.58, height 0.25
FP-3361P-MFG [mm]
  rect 1.19x3.3 smd paste+0 mask+0: 1(-2.54,-3.2) 2(0,3.2) 3(2.54,-3.2)
  silkscreen extent -3.48,-3.69 3.48,3.6, body extent -3.58,-4.95 3.58,4.95, height 0.25
FP-AC0603-MFG [mm]
  rect 0.9x0.8 smd paste+0 mask+0: 1(-0.85,0) 2(0.85,0)
  silkscreen extent -0.85,-0.82 0.85,0.82, body extent -1.4,-0.55 1.4,0.55, height 0.25
FP-CC0603-DA-MFG [mm]
  rect 0.8x0.9 smd paste+0 mask+0: 1(-0.75,0) 2(0.75,0)
  silkscreen extent -0.85,-0.85 0.85,0.85, body extent -1.35,-0.75 1.35,0.75, height 0.25
FP-CR0603-IPC_C [mm]
  rect 0.758x0.812 smd paste+0 mask+0: 1(-0.627,0) 2(0.627,0)
  silkscreen extent -1.01,-0.85 1.01,0.85, body extent -1.11,-0.55 1.11,0.55, height 0.25
FP-D0016A-MFG [mm]
  rect 1.55x0.6 smd paste-1000 mask+0: 1(-2.7,4.445) 2(-2.7,3.175) 3(-2.7,1.905) 4(-2.7,0.635) 5(-2.7,-0.635) 6(-2.7,-1.905) 7(-2.7,-3.175) 8(-2.7,-4.445) 9(2.7,-4.445) 10(2.7,-3.175) 11(2.7,-1.905) 12(2.7,-0.635) 13(2.7,0.635) 14(2.7,1.905) 15(2.7,3.175) 16(2.7,4.445)
  silkscreen extent -4.35,-5 1.55,5, body extent -3.57,-5.25 3.57,5.25, height 0.25
FP-ERBRD-MFG [mm]
  rect 0.475x0.5 smd paste+0 mask+0: 1(-0.512,0) 2(0.513,0)
  silkscreen extent -0.56,-0.67 0.55,0.67, body extent -0.85,-0.4 0.85,0.4, height 0.25
FP-GRM188-0_2-IPC_B [mm]
  rect 1.105x1.006 smd paste+0 mask+0: 1(-0.701,0) 2(0.701,0)
  silkscreen extent -1.25,-0.9 1.25,0.9, body extent -1.5,-0.75 1.5,0.75, height 0.25
FP-RT0603-MFG [mm]
  rect 0.9x0.8 smd paste+0 mask+0: 1(-0.85,0) 2(0.85,0)
  silkscreen extent -0.85,-0.81 0.86,0.8, body extent -1.4,-0.55 1.4,0.55, height 0.25
FP-SMBJ-MFG [mm]
  rect 2.16x2.26 smd paste+0 mask+0: 1(-2.45,0) 2(2.45,0)
  silkscreen extent -4.27,-1.97 2.37,1.97, body extent -3.63,-2.07 3.63,2.07, height 0.25
FP-SOT523-MFG [mm]
  rect 0.51x0.4 smd paste+0 mask+0: 1(-0.645,0.5) 2(-0.645,-0.5) 3(0.645,0)
  silkscreen extent -0.02,-0.85 0.43,0.85, body extent -0.81,-0.8 0.81,0.8, height 0.9
FP-TMM-102-03-T-S-MFG [mm]
  rect 1.39x1.39 hole 0.89 paste-2539.97 mask+0: 1(-1,0)
  round 1.39 hole 0.89 paste-2539.97 mask+0: 2(1,0)
  silkscreen extent -2.25,-2.67 2.25,1.02, body extent -2.1,-2.07 2.1,2.07, height 0.25
IND_ASPI-4030S-4R7M-T [mm]
  rect 1.1x3.4 smd: 1(-1.5,0) 2(1.5,0)
  silkscreen extent -0.63,-2 0.63,2, body extent -2,-2 2,2, height 3
P-SOP18-0812-1p27-001_TOS [mm]
  rect 1.561x0.486 smd paste+0 mask+0: 1(-4.737,5.08) 2(-4.737,3.81) 3(-4.737,2.54) 4(-4.737,1.27) 5(-4.737,0) 6(-4.737,-1.27) 7(-4.737,-2.54) 8(-4.737,-3.81) 9(-4.737,-5.08) 10(4.737,-5.08) 11(4.737,-3.81) 12(4.737,-2.54) 13(4.737,-1.27) 14(4.737,0) 15(4.737,1.27) 16(4.737,2.54) 17(4.737,3.81) 18(4.737,5.08)
  silkscreen extent -3.87,-5.88 6.03,5.88, body extent -5.16,-5.76 5.16,5.76, height 2.85
RESC0805(2012)_L [mm] "Chip Resistor, Body 2.0x1.3mm, IPC High Density"
  rrect25% 0.76x1.3 smd: 1(-0.9,0) 2(0.89,0)
  silkscreen extent -0.19,-0.55 0.18,0.55, body extent -1,-0.62 1,0.63, height 0.6
RESC1608X55X25LL10T15 [mm] "Chip Resistor, 2-Leads, Body 1.60x0.80mm, IPC High Density"
  rect 0.6x0.8 smd: 1(-0.65,0) 2(0.65,0)
  body extent -0.85,-0.45 0.85,0.45, height 0.55
RESC2013X70X40LL20T20 [mm] "Chip Resistor, 2-Leads, Body 2.00x1.25mm, IPC High Density"
  rect 0.95x1.35 smd: 1(-0.775,0) 2(0.775,0)
  body extent -1.1,-0.72 1.1,0.72, height 0.7
SOP18-P-375-1p27_TOS [mm]
  rect 1.411x0.451 smd paste+0 mask+0: 1(-4.8,5.08) 2(-4.8,3.81) 3(-4.8,2.54) 4(-4.8,1.27) 5(-4.8,0) 6(-4.8,-1.27) 7(-4.8,-2.54) 8(-4.8,-3.81) 9(-4.8,-5.08) 10(4.8,-5.08) 11(4.8,-3.81) 12(4.8,-2.54) 13(4.8,-1.27) 14(4.8,0) 15(4.8,1.27) 16(4.8,2.54) 17(4.8,3.81) 18(4.8,5.08)
  silkscreen extent -3.63,-6.63 6.01,6.63, body extent -6.47,-6.5 6.47,6.5, height 10.47
SOT583_MP2338_MNP [mm]
  rect 0.606x0.279 smd paste+0 mask+0: 1(-0.748,0.75) 2(-0.748,0.25) 3(-0.748,-0.25) 4(-0.748,-0.75) 5(0.748,-0.75) 6(0.748,-0.25) 7(0.748,0.25) 8(0.748,0.75)
  silkscreen extent -0.77,-1.23 0.77,1.23, body extent -0.85,-1.1 0.85,1.1, height 0.56
WE-LQS_6028 [mm] "SMD Power Inductor, 2-Leads, body 6x6mm"
  rect 1.8x5.7 smd: 1(2.3,0) 2(-2.3,0)
  silkscreen extent -1.07,-3.77 2.42,3.15, body extent -3,-3 3,3, height 2.83

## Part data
"A1 Cell Reset Decoder" "A1 Cell Set Decoder" "A1 Pin Reset Decoder" "A1 Pin Set Decoder" "A2 Cell Reset Decoder" "A2 Cell Set Decoder" "A2 Pin Reset Decoder" "A2 Pin Set Decoder": library part CMP-1633-00102-3, "IC 3-8 DECODER/DEMUX HS 16-SOIC", Ambient Temperature Range High=+125°C, Ambient Temperature Range Low=-55°C, Manufacturer="Texas Instruments", Max Junction Temp=+150°C, Max Supply Voltage=6V, Min Supply Voltage=2V, Package=D0016A, Quiescent Current=8uA, Temperature="-55°C to +125°C"
"A1 Reset Sink" "A1 Reset Source" "A1 Set Sink" "A1 Set Source" "A2 Reset Sink" "A2 Reset Source" "A2 Set Sink" "A2 Set Source": "Description", Manufacturer_Name="Toshiba Electronic Devices & Storage Corp."
A1C1 A1C2 A1C3 A1C4 A1C5 A1C6 A1C7 A1C8 A2C1 A2C2 A2C3 A2C4 A2C5 A2C6 A2C7 A2C8: library part BRAILLE-6
A1D1C1 A1D1C2 A1D1C3 A1D1C4 A1D1C5 A1D1C6 A1D1C7 A1D1C8 A1D2C1 A1D2C2 A1D2C3 A1D2C4 A1D2C5 A1D2C6 A1D2C7 A1D2C8 A1D3C1 A1D3C2 A1D3C3 A1D3C4 A1D3C5 A1D3C6 A1D3C7 A1D3C8 A1D4C1 A1D4C2 A1D4C3 A1D4C4 A1D4C5 A1D4C6 A1D4C7 A1D4C8 A1D5C1 A1D5C2 A1D5C3 A1D5C4 A1D5C5 A1D5C6 A1D5C7 A1D5C8 A1D6C1 A1D6C2 A1D6C3 A1D6C4 A1D6C5 A1D6C6 A1D6C7 A1D6C8 A1D7C1 A1D7C2 A1D7C3 A1D7C4 A1D7C5 A1D7C6 A1D7C7 A1D7C8 A2D1C1 A2D1C2 A2D1C3 A2D1C4 A2D1C5 A2D1C6 A2D1C7 A2D1C8 A2D2C1 A2D2C2 A2D2C3 A2D2C4 A2D2C5 A2D2C6 A2D2C7 A2D2C8 A2D3C1 A2D3C2 A2D3C3 A2D3C4 A2D3C5 A2D3C6 A2D3C7 A2D3C8 A2D4C1 A2D4C2 A2D4C3 A2D4C4 A2D4C5 A2D4C6 A2D4C7 A2D4C8 A2D5C1 A2D5C2 A2D5C3 A2D5C4 A2D5C5 A2D5C6 A2D5C7 A2D5C8 A2D6C1 A2D6C2 A2D6C3 A2D6C4 A2D6C5 A2D6C6 A2D6C7 A2D6C8 A2D7C1 A2D7C2 A2D7C3 A2D7C4 A2D7C5 A2D7C6 A2D7C7 A2D7C8: library part CMP-12791-000024-1, "DIODE ARRAY GP 85V 75MA SOT523", Capacitance=1.5pF, Forward Current=75mA, Manufacturer="Diodes Inc.", Max Junction Temp=+150°C, Max Repetitive Reverse Voltage=85V, Max Surge Forward Current=0.5A, Package=SOT523, Peak Reverse Current=2uA, Temperature="-65°C to +150°C", Temperature Range Low=-65°C
"Back Button" "Forward Button" LED "Power Switch": library part CMP-02766-001621-1, "CONN HEADER VERT 2POS 2MM", Color=Black, Max Current Rating=3.9A, Max Operating Temperature=105°C, Max Voltage Rating (AC)=500V, Min Operating Temperature=-55°C, Package Quantity=1
"Battery Holder": "BATTERY HOLDER AA 4 CELL PC PIN", Package=None
C1_D C1_MCU C2_D C3_D C4_D C5_D C6_D C7_D C8_D C9_D C10_D C11_D C12_D C13_D C14_D C15_D C16_D: library part CMP-1036-04393-1, "CAP 100nF 10V ±5% 0805 (2012 Metric) Thickness 1mm SMD", Case-EIA=0805, Case-Metric=2012, Rated Voltage="10 V", Tolerance=Â±5%
CBST1 CBST2 Cin3 Cin6: library part CMP-45632-000007-1, "CAP CER 0.1UF 50V X7R 0603", Capacitance=100nF, Case Code (Imperial)=0603, Case Code (Metric)=1608, Dielectric=X7R, Max Operating Temperature=125°C, Min Operating Temperature=-55°C, Tolerance=10%, Voltage Rating=50V
CFF1 CFF2: library part CMP-1035-01681-2, "VJ0603Y471KXBAC", Manufacturer=Vitramon
Cin1 Cin2 Cin4 Cin5: library part CMP-1035-02796-1, "CAP 10uF 6.3V ±10% 0603 (1608 Metric) Thickness 1mm SMD", Case-EIA=0603, Case-Metric=1608, Rated Voltage="6.3 V", Tolerance=Â±10%
Cout1 Cout2 Cout3 Cout4: library part CMP-06035-001854-1, "Chip Multilayer Ceramic Capacitors for General Purpose, 0603, 22uF, X6S, 22%, 20%, 6.3V GRM188C80J226ME15D", Case Code (Imperial)=0603, Case Code (Metric)=1608, Dielectric=X6S, Max Operating Temperature=105°C, Min Operating Temperature=-55°C, Package Quantity=4000, Tolerance=20%, Voltage Rating=6.3V
CSS1 CSS2: library part CMP-03422-000397-1, "CC0603 22 nF X7R 20.00% 50 V", Capacitance="22 nF", Manufacturer=YAGEO, Manufacturer Part Number=CC0603MRX7R9BB223, Package=CC0603-DA, Temperature="-55°C to +125°C", Temperature Characteristic=X7R, Temperature Coefficient=15%, Temperature Range High=+125°C, Temperature Range Low=-55°C, Tolerance=0.2, Voltage="50 V"
Fuse1: library part CMP-05590-000001-1, "FUSE BOARD MOUNT 2A 32VDC 0402", Fuse Current=2A, Fuse Interrupt Dc Current=35A, Manufacturer="Panasonic Electronic Components", Max Fuse Dc Voltage=32V, Package=ERBRD, Resistance=53mΩ, Temperature="-40°C to +125°C", Temperature Range High=+125°C, Temperature Range Low=-40°C
L1: library part CMP-1354-00061-2, "74404063068", Ambient Temperature Range High=85°C, Ambient Temperature Range Low=-40°C, Case/Package=Nonstandard, Current Rating=2.4A, DC Resistance (DCR)=47mΩ, Inductance=6.8µH, Inductance Tolerance=20%, Max Operating Temperature=125°C, Saturation Current=2.8A, Self Resonant Frequency=40MHz, Series Resistance=61.1mΩ, Test Frequency=100kHz
L2: library part ASPI-4030S-4R7M-T, "4.7 ÂµH Shielded Drum Core, Wirewound Inductor 2 A 60mOhm Nonstandard ASPI-4030S-4R7M-T", Package=Package
MCU: library part CMP-0095-00013-2, "8-bit AVR Microcontroller, 32KB Flash, 1KB EEPROM, 2KB SRAM, 28-pin PDIP, Industrial Grade (-40°C to 85°C)"
"Pmod MicroSD Header": "Description", Manufacturer_Name=Sullins
R_LED: library part CMP-009-00102-2, "470R 0.125W 5% 0805 (2012 Metric)  SMD", Case/Package=0805, Power=125mW, Tolerance=5%
RDown_EN: library part CMP-2001-00401-1, "ERJ-6GEYJ333V", Manufacturer=Panasonic
RFB1 RFB3: library part CMP-2000-04226-1, "RC0603FR-1351KL", Manufacturer=Yageo
RFB2: library part CMP-07231-003312-1, "Thick Film Chip Resistors 0603 9.09kΩ 0.1W 1% 100ppm/°C  CR0603-FX-9091ELF", Case Code (Imperial)=0603, Case Code (Metric)=1608, Max Operating Temperature=155°C, Max Power Dissipation=100mW, Min Operating Temperature=-55°C, Package Quantity=5000, Resistance=9.09kR, Temperature Coefficient=100ppm/°C, Tolerance=1%, Voltage Rating=50V
"RFB4_Fixed 10K" RT1 RT2: library part CMP-03412-024264-1, "RT0603 10KΩ 0.1W 50 ppm/°C 1.00% RT0603FRE1010KL", Manufacturer=Yageo, Manufacturer Part Number=RT0603FRE1010KL, Package=RT0603, Power Rating=0.1W, Resistance=10KΩ, Temperature="-55°C to +155°C", Temperature Coefficient="50 ppm/°C", Temperature Range High=+155°C, Temperature Range Low=-55°C, Tolerance=0.01, Voltage Rating=75V
RPG1 RPG2: library part CMP-03412-022575-2, "RES 100KΩ 1.00% 0.1W 0603 AC0603FR-10100KL", Case/Package=0603, Resistance=100kR, Tolerance=1%
Rup_EN: library part CMP-2001-00442-1, "ERJ-6GEYJ683V", Manufacturer=Panasonic
"RVFB4_Var 50K": library part CMP-07234-000057-1, "TRIMMER 50K OHM 0.5W GW TOP ADJ", Color=Natural, Max Operating Temperature=125°C, Max Power Dissipation=500mW, Min Operating Temperature=-55°C, Package Quantity=1, Resistance=50kR, Resistance Tolerance=10%, Resistor Type=Cermet, Temperature Coefficient=100ppm/°C, Voltage Rating=300V
SKD SKD1 SKD2 SKDB: library part CMP-2000-04943-2, "DIODE SCHOTTKY 40V 1A SMA", Forward Current=1A, Manufacturer="ON Semiconductor", Max Junction Temp=+125°C, Max Repetitive Reverse Voltage=40V, Max Surge Forward Current=40A, Package=403AE, Peak Reverse Current=0.2mA, Temperature="-65°C to +125°C", Temperature Range Low=-65°C
TVS: library part CMP-2000-07093-2, "TVS DIODE 12V 19.9V DO214AA", Breakdown Voltage=13.3V, Clamping Voltage=19.9V, Manufacturer=Littelfuse, Max Junction Temp=+150°C, Package=SMBJ, Peak Pulse Current=30.2A, Peak Pulse Power=600W, Reverse Standoff Voltage=12V, Temperature="-65°C to +150°C", Temperature Range Low=-65°C
"V_Drive Buck" "VCC Buck": "High-Efficiency 28V 3A 450kHz Synchronous Step-Down Converter In SOT583 Package", Manufacturer_Name="Monolithic Power Systems"

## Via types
v1: diameter 0.7, hole 0.3, Top Layer to Bottom Layer, 308 vias
v2: diameter 1.27, hole 0.711, Top Layer to Bottom Layer, 37 vias

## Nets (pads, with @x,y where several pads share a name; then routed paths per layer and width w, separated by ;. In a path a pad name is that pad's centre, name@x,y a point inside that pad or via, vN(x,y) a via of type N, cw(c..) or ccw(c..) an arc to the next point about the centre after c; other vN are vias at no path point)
"A1 Cell1": "A1 Set Sink.11" A1D7C1.2 | length 46.6
  Top Layer w0.5: v1(14.746,39.705) 14.746,41.097 15.403,41.754 33.995,41.754 34.546,42.305 34.546,65.895 34.536,65.905
  Bottom Layer w0.5: A1D7C1.2@14.746,38.45 v1(14.746,39.705)
"A1 Cell1 Reset": "A1 Reset Source.11" A1D7C1.1 | length 77.7
  Top Layer w0.5: 69.536,65.805 69.541,65.8 69.541,57.91 v1@69.546,57.905
  Bottom Layer w0.5: A1D7C1.1@13.746,38.45 13.746,40.931 20.242,47.427 66.768,47.427 69.541,50.2 69.541,57.9 v1@69.546,57.905
  other v1: 69.546,58.005
"A1 Cell2": "A1 Set Sink.12" A1D7C2.2 | length 38
  Top Layer w0.5: v1(23.746,39.705) 25.168,41.127 34.568,41.127 35.806,42.365 35.806,65.905
  Bottom Layer w0.5: A1D7C2.2@23.746,38.45 v1(23.746,39.705)
"A1 Cell2 Reset": "A1 Reset Source.12" A1D7C2.1 | length 71
  Top Layer w0.5: 70.806,65.805 70.806,57.945 v1@70.846,57.905
  Bottom Layer w0.5: A1D7C2.1@22.746,38.45 22.746,42.005 27.541,46.8 68.041,46.8 70.846,49.605 v1@70.846,57.905
  other v1: 70.846,58.005
"A1 Cell3": "A1 Set Sink.13" A1D7C3.2 | length 30.6
  Top Layer w0.5: v1(32.746,39.705) 32.784,39.743 32.784,39.884 32.799,39.899 32.799,40.207 33.092,40.5 35.441,40.5 37.076,42.135 37.076,65.905
  Bottom Layer w0.5: A1D7C3.2@32.746,38.45 v1(32.746,39.705)
"A1 Cell3 Reset": "A1 Reset Source.13" A1D7C3.1 | length 63.7
  Top Layer w0.5: v1@72.046,57.905 72.061,57.92 72.061,65.79 72.076,65.805
  Bottom Layer w0.5: A1D7C3.1@31.746,38.45 31.746,42.105 35.768,46.127 69.368,46.127 72.046,48.805 v1@72.046,57.905
  other v1: 72.046,58.005
"A1 Cell4": "A1 Set Sink.14" A1D7C4.2 | length 30.4
  Top Layer w0.5: 38.346,65.905 38.346,40.305 39.105,39.546 v1(41.746,39.546)
  Bottom Layer w0.5: A1D7C4.2@41.746,38.45 v1(41.746,39.546)
"A1 Cell4 Reset": "A1 Reset Source.14" A1D7C4.1 | length 56.3
  Top Layer w0.5: v1@73.346,57.905 73.346,65.805
  Bottom Layer w0.5: A1D7C4.1@40.746,38.45 40.746,42.105 44.141,45.5 70.541,45.5 73.346,48.305 v1@73.346,57.905
  other v1: 73.346,58.005
"A1 Cell5": "A1 Set Sink.15" A1D7C5.2 | length 38
  Top Layer w0.5: 39.616,65.905 39.616,40.629 39.972,40.273 42.047,40.273 42.615,39.705 v1(50.746,39.705)
  Bottom Layer w0.5: A1D7C5.2@50.746,38.45 v1(50.746,39.705)
"A1 Cell5 Reset": "A1 Reset Source.15" A1D7C5.1 | length 49.7
  Top Layer w0.5: 74.616,65.805 74.652,65.769 74.652,57.94 v1@74.687,57.905
  Bottom Layer w0.5: A1D7C5.1@49.746,38.45 49.746,42.505 52.068,44.827 72.468,44.827 74.687,47.046 v1@74.687,57.905
  other v1: 74.687,58.005
"A1 Cell6": "A1 Set Sink.16" A1D7C6.2 | length 46
  Top Layer w0.5: 40.886,65.905 40.886,41.193 41.179,40.9 59.453,40.9 59.746,40.607 v1(59.746,39.705)
  Bottom Layer w0.5: A1D7C6.2@59.746,38.45 v1(59.746,39.705)
"A1 Cell6 Reset": "A1 Reset Source.16" A1D7C6.1 | length 42.3
  Top Layer w0.5: 75.886,65.805 75.916,65.775 75.916,57.935 v1@75.946,57.905
  Bottom Layer w0.5: A1D7C6.1@58.746,38.45 58.746,42.505 60.441,44.2 73.741,44.2 75.946,46.405 v1@75.946,57.905
  other v1: 75.946,58.005
"A1 Cell7": "A1 Set Sink.17" A1D7C7.2 | length 53.5
  Top Layer w0.5: 42.156,65.905 42.156,41.82 42.449,41.527 68.175,41.527 68.746,40.956 v1(68.746,39.874)
  Bottom Layer w0.5: A1D7C7.2@68.746,38.45 v1(68.746,39.874)
"A1 Cell7 Reset": "A1 Reset Source.17" A1D7C7.1 | length 34.9
  Top Layer w0.5: v1(77.146,58.005) 77.156,58.015 77.156,65.805
  Bottom Layer w0.5: A1D7C7.1@67.746,38.45 67.746,42.505 68.646,43.405 74.846,43.405 77.146,45.705 v1(77.146,58.005)
"A1 Cell8": "A1 Set Sink.18" A1D7C8.2 | length 61.3
  Top Layer w0.5: 43.426,65.905 43.426,42.447 43.719,42.154 77.148,42.154 77.746,41.556 v1(77.746,39.874)
  Bottom Layer w0.5: A1D7C8.2@77.746,38.45 v1(77.746,39.874)
"A1 Cell8 Reset": "A1 Reset Source.18" A1D7C8.1 | length 28.1
  Top Layer w0.5: 78.426,65.805 78.457,65.774 78.457,57.904 v1@78.487,57.874
  Bottom Layer w0.5: A1D7C8.1@76.746,38.45 76.746,43.296 78.487,45.037 v1@78.487,57.874
  other v1: 78.487,58.005
"A1 Pin1": "A1 Set Source.18" A1D1C1.1 A1D1C2.1 A1D1C3.1 A1D1C4.1 A1D1C5.1 A1D1C6.1 A1D1C7.1 A1D1C8.1 | length 126.3
  Top Layer w0.5: v1@22.246,52.012 22.246,50.919 20.123,48.797 18.897,48.797 9.276,39.176 9.276,27.656 10.428,26.505 v1(16.246,26.505) v1(25.246,26.505) v1(34.135,26.505) v1(43.246,26.505) v1(52.135,26.505) v1(61.246,26.505) v1(70.135,26.505) v1(79.146,26.505) ; 25.826,65.905 25.826,52.125 v1(25.846,52.105)
  Bottom Layer w0.5: A1D1C1.1@16.235,25.487 16.241,25.492 16.241,26.499 v1(16.246,26.505) ; v1(22.246,52.105) v1(25.846,52.105) ; A1D1C2.1@25.241,25.392 v1@25.241,26.399 ; A1D1C3.1@34.13,25.494 v1@34.13,26.501 ; A1D1C4.1@43.241,25.392 v1@43.241,26.399 ; A1D1C5.1@52.13,25.494 v1@52.13,26.501 ; A1D1C6.1@61.241,25.392 v1@61.241,26.399 ; A1D1C7.1@70.13,25.494 v1@70.13,26.501 ; A1D1C8.1@79.141,25.392 v1@79.141,26.399
"A1 Pin1 Reset": "A1 Reset Sink.18" A1D1C1.2 A1D1C2.2 A1D1C3.2 A1D1C4.2 A1D1C5.2 A1D1C6.2 A1D1C7.2 A1D1C8.2 | length 179.3
  Top Layer w0.5: v1(12.246,29.405) 14.673,29.405 14.773,29.305 v1(17.246,29.305) v1(26.246,29.305) v1(35.246,29.305) v1(44.246,29.305) v1(53.246,29.305) v1(62.246,29.305) v1(71.346,29.305) v1(80.246,29.305) ; 60.826,65.805 60.836,65.795 60.836,57.915 v1(60.846,57.905)
  Bottom Layer w0.5: v1(12.246,29.405) 12.246,41.286 19.06,48.1 60.241,48.1 60.846,48.705 v1(60.846,57.905) ; A1D1C1.2@17.235,25.487 17.241,25.492 17.241,29.299 v1(17.246,29.305) ; A1D1C2.2@26.241,25.492 v1@26.241,29.299 ; A1D1C3.2@35.241,25.492 v1@35.241,29.299 ; A1D1C4.2@44.241,25.492 v1@44.241,29.299 ; A1D1C5.2@53.241,25.492 v1@53.241,29.299 ; A1D1C6.2@62.241,25.492 v1@62.241,29.299 ; A1D1C7.2@71.241,25.392 71.241,29.133 71.346,29.238 v1(71.346,29.305) ; A1D1C8.2@80.241,25.492 v1@80.241,29.299
"A1 Pin2": "A1 Set Source.17" A1D2C1.1 A1D2C2.1 A1D2C3.1 A1D2C4.1 A1D2C5.1 A1D2C6.1 A1D2C7.1 A1D2C8.1 | length 112.9
  Top Layer w0.5: 24.556,65.905 24.556,51.456 20.505,47.405 19.338,47.405 12.146,40.213 12.146,34.005 13.623,32.528 v1@77.846,32.528
  Bottom Layer w0.5: v1@14.946,32.528 v1@14.956,32.518 ; A1D2C1.1@14.956,31.293 A1D2C1.1@14.965,31.284 ; A1D2C1.1@14.956,31.426 v1@14.956,32.528 ; A1D2C2.1@23.956,31.426 v1@23.956,32.528 ; A1D2C3.1@32.845,31.426 v1@32.845,32.528 ; A1D2C4.1@41.956,31.426 v1@41.956,32.528 ; A1D2C5.1@50.845,31.426 v1@50.845,32.528 ; A1D2C6.1@59.956,31.426 v1@59.956,32.528 ; A1D2C7.1@68.845,31.426 v1@68.845,32.528 ; A1D2C8.1@77.856,31.426 v1@77.856,32.528
  other v1: 14.946,32.405 23.946,32.405 32.835,32.405 41.946,32.405 50.835,32.405 59.946,32.405 68.835,32.405 77.846,32.405
"A1 Pin2 Reset": "A1 Reset Sink.17" A1D2C1.2 A1D2C2.2 A1D2C3.2 A1D2C4.2 A1D2C5.2 A1D2C6.2 A1D2C7.2 A1D2C8.2 | length 152.3
  Top Layer w0.5: v1(11.227,31.305) v1(26.246,31.305) v1(35.246,31.305) v1(44.246,31.305) v1(53.246,31.305) v1(62.246,31.305) 62.313,31.305 62.413,31.205 v1(71.246,31.205) 71.313,31.205 71.413,31.305 v1(80.246,31.305) ; v1(59.546,57.905) 59.551,57.91 59.551,65.8 59.556,65.805
  Bottom Layer w0.5: v1(11.227,31.305) 11.227,36.176 11.146,36.256 11.146,41.073 18.8,48.727 50.368,48.727 v1(59.546,57.905) ; A1D2C1.2@15.965,31.284 15.976,31.294 17.236,31.294 v1(17.246,31.305) ; A1D2C2.2@24.976,31.294 v1@26.236,31.294 ; A1D2C3.2@33.976,31.294 v1@35.236,31.294 ; A1D2C4.2@42.976,31.294 v1@44.236,31.294 ; A1D2C5.2@51.976,31.294 v1@53.236,31.294 ; A1D2C6.2@60.976,31.294 v1@62.236,31.294 ; A1D2C7.2@69.976,31.194 v1@71.236,31.194 ; A1D2C8.2@78.976,31.294 v1@80.236,31.294
"A1 Pin3": "A1 Set Source.16" A1D3C1.1 A1D3C2.1 A1D3C3.1 A1D3C4.1 A1D3C5.1 A1D3C6.1 A1D3C7.1 A1D3C8.1 | length 127.3
  Top Layer w0.5: 23.286,65.905 23.286,51.073 20.245,48.032 19.078,48.032 9.946,38.899 9.946,27.873 10.414,27.405 v1(31.546,27.405) v1(40.746,27.405) v1(49.546,27.405) v1(58.746,27.405) 58.785,27.366 67.607,27.366 v1(67.646,27.405) v1(76.746,27.405)
  Bottom Layer w0.5: v1(13.546,27.405) 13.546,27.338 13.695,27.189 A1D3C1.1@13.695,25.487 ; v1(22.546,27.405) 22.546,27.338 22.695,27.189 22.695,25.438 A1D3C2.1@22.721,25.412 ; v1(31.546,27.405) 31.546,27.338 31.695,27.189 31.695,25.587 A1D3C3.1@31.622,25.514 ; A1D3C4.1@40.721,25.412 40.721,27.379 v1(40.746,27.405) ; v1(49.546,27.405) 49.546,27.338 49.695,27.189 49.695,25.587 A1D3C5.1@49.622,25.514 ; A1D3C6.1@58.721,25.412 58.721,27.379 v1(58.746,27.405) ; A1D3C7.1@67.61,25.514 67.671,25.575 67.671,27.38 v1(67.646,27.405) ; A1D3C8.1@76.621,25.412 76.746,25.538 76.721,25.563 76.721,27.379 v1(76.746,27.405)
